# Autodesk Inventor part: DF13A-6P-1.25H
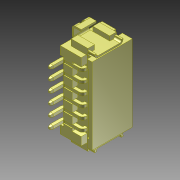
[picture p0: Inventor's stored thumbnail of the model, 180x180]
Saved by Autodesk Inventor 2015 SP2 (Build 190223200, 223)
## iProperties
Created: 2016-03
Part Number: DF13A-6P-1.25H
Material: Allgemein
Document SubType Name: Modeling
Designer: ryll
Mass: 0.0911838 g
Surface Area: 3.44831 cm^2
Volume: 0.0911838 cm^3
Density: 1 g/cm^3
Appearance: Vorgabe
Author: ryll
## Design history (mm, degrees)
node "DF13A-6P-1.25H"
node "Volumenkörper1"
node "Basis1"
